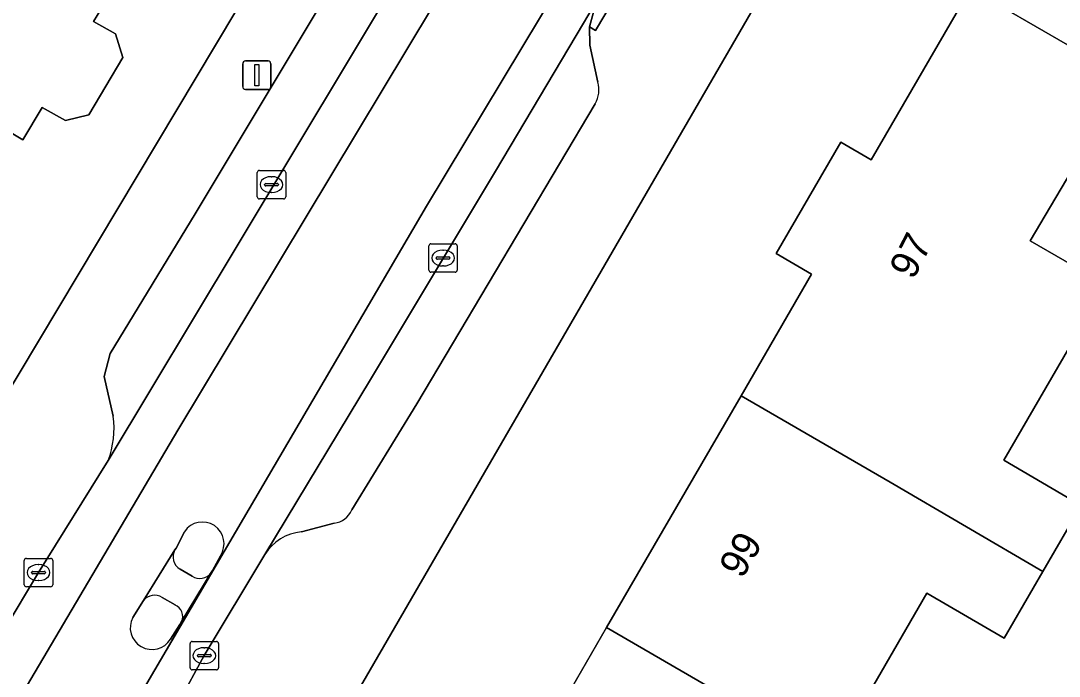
# Model space of a CAD drawing. Extents: x 160349 to 161355, y 381727 to 382854.
# Drawn here: x 160778.71 to 160815.25, y 382183.88 to 382206.95 of the extents above; entities that cross this region are included whole.
import ezdxf

# ---------------------------------------------------------------- set-up
doc = ezdxf.new("R2010")
doc.units = 0
for name, color, linetype in [('IMGEO_Erf', 7, 'Continuous'), ('IMGEO_Kolk', 7, 'Continuous'), ('IMGEO_Lichtmast', 7, 'Continuous'), ('IMGEO_Pand', 7, 'Continuous'), ('IMGEO_Pand_nummerreeks', 7, 'Continuous'), ('IMGEO_Parkeervlak_open', 7, 'Continuous'), ('IMGEO_Rijbaan_lokaal_gesloten', 7, 'Continuous'), ('IMGEO_Verkeerseiland_open', 7, 'Continuous'), ('IMGEO_Voetpad_open', 7, 'Continuous')]:
    doc.layers.add(name, color=color, linetype=linetype)

msp = doc.modelspace()

# ---------------------------------------------------------------- linework, layer by layer
at = {"layer": 'IMGEO_Erf'}
for points in [[(160933.344, 382182.327), (160924.218, 382191.389), (160906.426, 382206.128), (160902.418, 382205.455), (160886.177, 382214.66), (160875.171, 382221.124), (160873.887, 382226.28), (160832.686, 382250), (160830.042, 382251.522), (160829.161, 382250), (160786.376, 382176.128), (160847.679, 382140.543), (160850.05, 382144.635)], [(160761.313, 382208.139), (160764.737, 382206.09), (160765.095, 382206.689), (160769.767, 382203.894), (160771.061, 382206.058), (160774.047, 382204.271), (160778.338, 382201.704), (160775.107, 382196.304), (160771.946, 382191.02), (160769.713, 382187.288), (160767.853, 382186.821), (160772.407, 382184.113), (160794.573, 382221.181)], [(160781.915, 382207.991), (160781.273, 382206.918), (160782.047, 382206.482), (160782.296, 382205.652), (160781.107, 382203.64), (160780.279, 382203.438), (160779.466, 382203.898), (160778.785, 382202.76), (160774.494, 382205.327), (160771.787, 382206.947), (160768.599, 382208.851)], [(160796.673, 382181.019), (160799.321, 382185.589), (160804.051, 382193.749), (160806.533, 382198.033), (160805.285, 382198.756), (160807.566, 382202.676), (160808.629, 382202.058), (160812.129, 382208.085), (160817.811, 382204.787)], [(160817.455, 382204.671), (160814.224, 382199.199), (160816.882, 382197.66), (160813.3, 382191.479), (160816.016, 382189.892), (160814.665, 382187.559), (160813.31, 382185.219), (160810.592, 382186.807), (160807.24, 382181.022)]]:
    msp.add_lwpolyline(points, dxfattribs=at)
at = {"layer": 'IMGEO_Kolk'}
for p, q in [((160787.029, 382200.754), (160787.029, 382201.606)), ((160787.104, 382201.68), (160787.956, 382201.68)), ((160787.517, 382201.46), (160787.542, 382201.46)), ((160788.03, 382201.606), (160788.03, 382200.754)), ((160787.288, 382201.174), (160787.288, 382201.186)), ((160787.726, 382201.137), (160787.328, 382201.137)), ((160787.331, 382201.223), (160787.729, 382201.223)), ((160787.772, 382201.186), (160787.772, 382201.174)), ((160787.54, 382200.9), (160787.515, 382200.9)), ((160787.956, 382200.68), (160787.104, 382200.68)), ((160793.066, 382198.171), (160793.066, 382199.023)), ((160793.141, 382199.097), (160793.993, 382199.097)), ((160794.067, 382199.023), (160794.067, 382198.171)), ((160793.325, 382198.591), (160793.325, 382198.603)), ((160793.763, 382198.554), (160793.365, 382198.554)), ((160793.368, 382198.64), (160793.766, 382198.64)), ((160793.554, 382198.877), (160793.579, 382198.877)), ((160793.809, 382198.603), (160793.809, 382198.591)), ((160793.577, 382198.317), (160793.552, 382198.317)), ((160793.993, 382198.097), (160793.141, 382198.097)), ((160778.832, 382187.101), (160778.832, 382187.953)), ((160778.907, 382188.027), (160779.759, 382188.027)), ((160779.833, 382187.953), (160779.833, 382187.101)), ((160779.32, 382187.807), (160779.345, 382187.807)), ((160779.091, 382187.521), (160779.091, 382187.533)), ((160779.529, 382187.484), (160779.131, 382187.484)), ((160779.134, 382187.57), (160779.532, 382187.57)), ((160779.343, 382187.247), (160779.318, 382187.247)), ((160779.575, 382187.533), (160779.575, 382187.521)), ((160779.759, 382187.027), (160778.907, 382187.027)), ((160784.667, 382184.178), (160784.667, 382185.03)), ((160784.742, 382185.104), (160785.594, 382185.104)), ((160785.668, 382185.03), (160785.668, 382184.178)), ((160785.155, 382184.884), (160785.18, 382184.884)), ((160784.926, 382184.598), (160784.926, 382184.61)), ((160785.364, 382184.561), (160784.966, 382184.561)), ((160784.969, 382184.647), (160785.367, 382184.647)), ((160785.178, 382184.324), (160785.153, 382184.324)), ((160785.41, 382184.61), (160785.41, 382184.598)), ((160785.594, 382184.104), (160784.742, 382184.104))]:
    msp.add_line(p, q, dxfattribs=at)
for points in [[(160787.029, 382200.754), (160787.029, 382201.606)], [(160787.104, 382201.68), (160787.956, 382201.68)], [(160788.03, 382201.606), (160788.03, 382200.754)], [(160787.956, 382200.68), (160787.104, 382200.68)], [(160793.066, 382198.171), (160793.066, 382199.023)], [(160793.141, 382199.097), (160793.993, 382199.097)], [(160794.067, 382199.023), (160794.067, 382198.171)], [(160793.993, 382198.097), (160793.141, 382198.097)], [(160778.832, 382187.101), (160778.832, 382187.953)], [(160778.907, 382188.027), (160779.759, 382188.027)], [(160779.833, 382187.953), (160779.833, 382187.101)], [(160779.759, 382187.027), (160778.907, 382187.027)], [(160784.667, 382184.178), (160784.667, 382185.03)], [(160784.742, 382185.104), (160785.594, 382185.104)], [(160785.668, 382185.03), (160785.668, 382184.178)], [(160785.594, 382184.104), (160784.742, 382184.104)]]:
    msp.add_lwpolyline(points, dxfattribs=at)
for centre, radius, start, end in [((160787.106, 382201.604), 0.0765, 91.552, 178.448), ((160787.106, 382201.604), 0.0765, 91.552, 178.448), ((160787.954, 382201.604), 0.0765, 1.552, 88.448), ((160787.954, 382201.604), 0.0765, 1.552, 88.448), ((160787.328, 382201.183), 0.0403, 85.8775, 175.7526), ((160787.325, 382201.173), 0.0366, 178.938, 274.7102), ((160787.729, 382201.18), 0.043, 264.8664, 352.4533), ((160787.733, 382201.185), 0.0386, 1.7309, 96.639), ((160787.106, 382200.756), 0.0765, 181.552, 268.448), ((160787.106, 382200.756), 0.0765, 181.552, 268.448), ((160787.954, 382200.756), 0.0765, 271.552, 358.448), ((160787.954, 382200.756), 0.0765, 271.552, 358.448), ((160793.143, 382199.021), 0.0765, 91.552, 178.448), ((160793.143, 382199.021), 0.0765, 91.552, 178.448), ((160793.991, 382199.021), 0.0765, 1.552, 88.448), ((160793.991, 382199.021), 0.0765, 1.552, 88.448), ((160793.365, 382198.6), 0.0403, 85.8775, 175.7526), ((160793.362, 382198.59), 0.0366, 178.938, 274.7102), ((160793.766, 382198.597), 0.043, 264.8664, 352.4533), ((160793.77, 382198.602), 0.0386, 1.7309, 96.639), ((160793.143, 382198.173), 0.0765, 181.552, 268.448), ((160793.143, 382198.173), 0.0765, 181.552, 268.448), ((160793.991, 382198.173), 0.0765, 271.552, 358.448), ((160793.991, 382198.173), 0.0765, 271.552, 358.448), ((160778.909, 382187.951), 0.0765, 91.552, 178.448), ((160778.909, 382187.951), 0.0765, 91.552, 178.448), ((160779.757, 382187.951), 0.0765, 1.552, 88.448), ((160779.757, 382187.951), 0.0765, 1.552, 88.448), ((160779.131, 382187.53), 0.0403, 85.8775, 175.7526), ((160779.128, 382187.52), 0.0366, 178.938, 274.7102), ((160779.532, 382187.527), 0.043, 264.8664, 352.4533), ((160779.536, 382187.532), 0.0386, 1.7309, 96.639), ((160778.909, 382187.103), 0.0765, 181.552, 268.448), ((160778.909, 382187.103), 0.0765, 181.552, 268.448), ((160779.757, 382187.103), 0.0765, 271.552, 358.448), ((160779.757, 382187.103), 0.0765, 271.552, 358.448), ((160784.744, 382185.028), 0.0765, 91.552, 178.448), ((160784.744, 382185.028), 0.0765, 91.552, 178.448), ((160785.592, 382185.028), 0.0765, 1.552, 88.448), ((160785.592, 382185.028), 0.0765, 1.552, 88.448), ((160784.966, 382184.607), 0.0403, 85.8775, 175.7526), ((160784.963, 382184.597), 0.0366, 178.938, 274.7102), ((160785.367, 382184.604), 0.043, 264.8664, 352.4533), ((160785.371, 382184.609), 0.0386, 1.7309, 96.639), ((160784.744, 382184.18), 0.0765, 181.552, 268.448), ((160784.744, 382184.18), 0.0765, 181.552, 268.448), ((160785.592, 382184.18), 0.0765, 271.552, 358.448), ((160785.592, 382184.18), 0.0765, 271.552, 358.448)]:
    msp.add_arc(centre, radius, start, end, dxfattribs=at)
for centre, major_axis, ratio, start_param, end_param in [((160787.516, 382201.18), (-0.387, 0.002), 0.722429, 4.712389, 7.853982), ((160787.541, 382201.18), (-0.39, 0.002), 0.717154, 1.570796, 4.712389), ((160793.553, 382198.597), (-0.387, 0.002), 0.722429, 4.712389, 7.853982), ((160793.578, 382198.597), (-0.39, 0.002), 0.717154, 1.570796, 4.712389), ((160779.319, 382187.527), (-0.387, 0.002), 0.722429, 4.712389, 7.853982), ((160779.344, 382187.527), (-0.39, 0.002), 0.717154, 1.570796, 4.712389), ((160785.154, 382184.604), (-0.387, 0.002), 0.722429, 4.712389, 7.853982), ((160785.179, 382184.604), (-0.39, 0.002), 0.717154, 1.570796, 4.712389)]:
    msp.add_ellipse(centre, major_axis=major_axis, ratio=ratio, start_param=start_param, end_param=end_param, dxfattribs=at)
at = {"layer": 'IMGEO_Lichtmast'}
for p, q in [((160786.618, 382205.531), (160787.408, 382205.531)), ((160787.408, 382205.531), (160786.618, 382205.531)), ((160786.518, 382204.631), (160786.518, 382205.431)), ((160786.518, 382205.431), (160786.518, 382204.631)), ((160787.508, 382205.431), (160787.508, 382204.631)), ((160787.508, 382204.631), (160787.508, 382205.431)), ((160787.408, 382204.531), (160786.618, 382204.531)), ((160786.618, 382204.531), (160787.408, 382204.531))]:
    msp.add_line(p, q, dxfattribs=at)
msp.add_lwpolyline([(160786.938, 382205.406), (160787.088, 382205.406), (160787.088, 382204.656), (160786.938, 382204.656), (160786.938, 382205.406)], dxfattribs=at)
for centre, start, end in [((160786.618, 382205.431), 90, 180), ((160786.618, 382205.431), 90, 180), ((160787.408, 382205.431), 0, 90), ((160787.408, 382205.431), 360, 90), ((160786.618, 382204.631), 180, 270), ((160786.618, 382204.631), 180, 270), ((160787.408, 382204.631), 270, 0), ((160787.408, 382204.631), 270, 0)]:
    msp.add_arc(centre, 0.1, start, end, dxfattribs=at)
at = {"layer": 'IMGEO_Pand'}
for points in [[(160771.727, 382214.075), (160771.622, 382213.901), (160771.376, 382213.49), (160770.149, 382211.44), (160768.554, 382212.392), (160767.004, 382209.803), (160768.599, 382208.851), (160771.787, 382206.947), (160774.494, 382205.327), (160778.785, 382202.76), (160779.466, 382203.898), (160780.279, 382203.438), (160781.107, 382203.64), (160782.296, 382205.652), (160782.047, 382206.482), (160781.273, 382206.918), (160781.915, 382207.991)], [(160804.051, 382193.749), (160809.301, 382190.706), (160814.665, 382187.559), (160816.016, 382189.892), (160813.3, 382191.479), (160816.882, 382197.66), (160814.224, 382199.199), (160817.455, 382204.671), (160817.671, 382204.545), (160817.811, 382204.787), (160812.129, 382208.085), (160808.629, 382202.058), (160807.566, 382202.676), (160805.285, 382198.756), (160806.533, 382198.033)], [(160807.24, 382181.022), (160810.592, 382186.807), (160813.31, 382185.219), (160814.665, 382187.559), (160809.301, 382190.706), (160804.051, 382193.749), (160799.321, 382185.589), (160804.574, 382182.544)], [(160807.24, 382181.022), (160804.574, 382182.544), (160799.321, 382185.589), (160796.673, 382181.019), (160795.36, 382181.78), (160793.201, 382178.055), (160799.769, 382174.25), (160802.425, 382172.712), (160804.134, 382175.663), (160804.325, 382175.553), (160804.486, 382175.83), (160804.296, 382175.941), (160804.773, 382176.764), (160804.263, 382177.06), (160805.05, 382178.419), (160805.561, 382178.124), (160805.782, 382178.505), (160808.214, 382177.097), (160809.683, 382179.634)]]:
    msp.add_lwpolyline(points, close=True, dxfattribs=at)
at = {"layer": 'IMGEO_Parkeervlak_open'}
for points in [[(160781.786, 382191.466), (160786.323, 382199.028), (160798.28, 382218.963), (160805.521, 382230.961), (160817.325, 382250.962), (160826.186, 382266.882), (160838.167, 382290.047), (160842.376, 382298.812)], [(160839.013, 382296.685), (160829.617, 382277.989), (160823.877, 382267.074), (160820.834, 382261.421), (160816.429, 382253.709), (160815.075, 382251.417), (160814.238, 382250), (160812.776, 382247.525), (160807.918, 382239.299), (160796.693, 382219.912), (160784.85, 382200.156), (160781.859, 382195.236), (160781.646, 382194.422), (160781.963, 382193.031)], [(160799.013, 382204.786), (160798.729, 382206.085), (160798.713, 382206.735), (160798.962, 382207.633), (160798.503, 382206.859), (160795.414, 382201.651), (160791.017, 382194.317), (160787.293, 382188.166)], [(160790.359, 382189.731), (160792.641, 382193.471), (160798.922, 382204.027)], [(160788.58, 382188.958), (160789.734, 382189.265)]]:
    msp.add_lwpolyline(points, dxfattribs=at)
for centre, radius, start, end in [((160798.037, 382204.518), 1.012, 330.9649, 15.3615), ((160778.647, 382192.614), 3.343, 339.9207, 7.1739), ((160789.65, 382190.03), 0.769, 276.2553, 337.1612), ((160788.746, 382187.246), 1.72, 95.5483, 147.6668)]:
    msp.add_arc(centre, radius, start, end, dxfattribs=at)
at = {"layer": 'IMGEO_Rijbaan_lokaal_gesloten'}
for points in [[(160812.989, 382240.37), (160784.239, 382192.537), (160777.906, 382181.828), (160776.425, 382182.776), (160776.168, 382182.334), (160769.164, 382170.249), (160770.494, 382169.628), (160766.428, 382162.546), (160760.731, 382152.677), (160755.42, 382142.776), (160751.633, 382135.727), (160748.813, 382130.153), (160747.076, 382126.71), (160742.756, 382117.768), (160731.871, 382093.997), (160727.444, 382083.882), (160724.887, 382077.653), (160720.494, 382066.374), (160710.123, 382039.204), (160704.275, 382025.25)], [(160798.28, 382218.963), (160786.323, 382199.028), (160781.786, 382191.466), (160779.334, 382187.527), (160778.121, 382185.508), (160776.823, 382183.463), (160776.425, 382182.776), (160777.906, 382181.828), (160784.239, 382192.537), (160812.989, 382240.37)], [(160805.748, 382221.628), (160792.985, 382200.423), (160781.379, 382180.62), (160782.592, 382179.909), (160782.82, 382180.287), (160785.167, 382184.605), (160787.293, 382188.166), (160791.017, 382194.317), (160795.414, 382201.651), (160798.503, 382206.859), (160798.962, 382207.633)], [(160792.985, 382200.423), (160805.748, 382221.628)], [(160696.524, 381990.659), (160696.749, 381990.258), (160698.267, 381993.805), (160702.724, 382005.472), (160701.297, 382006.186), (160706.444, 382018.907), (160712.871, 382036.35), (160718.969, 382052.415), (160728.018, 382076.284), (160733.461, 382089.005), (160737.526, 382098.251), (160743.231, 382110.677), (160748.477, 382121.661), (160754.903, 382134.448), (160758.33, 382141.071), (160759.953, 382144.071), (160767.084, 382156.956), (160773.018, 382167.169), (160774.485, 382166.436), (160782.592, 382179.909), (160781.379, 382180.62), (160792.985, 382200.423)], [(160782.651, 382185.948), (160783.024, 382186.545), (160784.129, 382188.323), (160784.171, 382188.39), (160784.464, 382188.966)], [(160785.732, 382188.122), (160785.452, 382187.605)], [(160785.452, 382187.605), (160785.405, 382187.526), (160784.367, 382185.801), (160784.307, 382185.702), (160783.978, 382185.184)]]:
    msp.add_lwpolyline(points, dxfattribs=at)
for centre, radius, start, end in [((160785.098, 382188.544), 0.762, 326.3517, 146.3517), ((160783.326, 382185.587), 0.766, 151.8557, 328.2832)]:
    msp.add_arc(centre, radius, start, end, dxfattribs=at)
at = {"layer": 'IMGEO_Verkeerseiland_open'}
for points in [[(160784.464, 382188.966), (160784.171, 382188.39), (160784.129, 382188.323)], [(160784.129, 382188.323), (160783.024, 382186.545)], [(160785.405, 382187.526), (160785.452, 382187.605), (160785.732, 382188.122)], [(160784.737, 382187.404), (160784.311, 382187.652)], [(160784.311, 382187.652), (160784.737, 382187.404)], [(160784.367, 382185.801), (160785.405, 382187.526)], [(160783.024, 382186.545), (160782.651, 382185.948)], [(160783.683, 382186.65), (160784.138, 382186.386)], [(160784.138, 382186.386), (160783.683, 382186.65)], [(160783.978, 382185.184), (160784.307, 382185.702), (160784.367, 382185.801)]]:
    msp.add_lwpolyline(points, dxfattribs=at)
for centre, radius, start, end in [((160785.098, 382188.544), 0.762, 326.3517, 146.3517), ((160784.556, 382188.079), 0.492, 150.1813, 240.1699), ((160784.556, 382188.079), 0.492, 150.1813, 240.1699), ((160785.011, 382187.793), 0.476, 234.8447, 325.8555), ((160785.011, 382187.793), 0.476, 234.8447, 325.8555), ((160783.412, 382186.227), 0.502, 57.3746, 140.7313), ((160783.412, 382186.227), 0.502, 57.3746, 140.7313), ((160783.968, 382185.982), 0.438, 335.5793, 67.1767), ((160783.968, 382185.982), 0.438, 335.5793, 67.1767), ((160783.326, 382185.587), 0.766, 151.8557, 328.2832)]:
    msp.add_arc(centre, radius, start, end, dxfattribs=at)
at = {"layer": 'IMGEO_Voetpad_open'}
for points in [[(160843.818, 382306.679), (160846.821, 382312.974), (160844.409, 382314.087), (160840.283, 382305.069), (160838.339, 382300.821), (160828.746, 382282.08), (160815.558, 382257.479), (160811.234, 382250), (160794.573, 382221.181), (160772.407, 382184.113), (160770.967, 382181.708)], [(160781.963, 382193.031), (160781.646, 382194.422), (160781.859, 382195.236), (160784.85, 382200.156), (160796.693, 382219.912), (160807.918, 382239.299), (160812.776, 382247.525), (160812.345, 382247.775), (160813.659, 382250), (160814.643, 382251.667), (160815.075, 382251.417), (160816.429, 382253.709), (160820.834, 382261.421), (160823.877, 382267.074), (160829.617, 382277.989), (160839.013, 382296.685)], [(160785.65, 382171.897), (160786.376, 382176.128), (160829.161, 382250)], [(160824.181, 382246.765), (160816.635, 382233.947), (160808.563, 382220.384), (160808.01, 382219.333), (160806.44, 382220.243), (160804.931, 382217.699), (160805.361, 382217.445), (160802.26, 382212.214), (160801.83, 382212.468), (160800.434, 382210.12), (160800.864, 382209.866), (160798.933, 382206.605), (160798.713, 382206.735), (160798.729, 382206.085), (160799.013, 382204.786)], [(160798.922, 382204.027), (160792.641, 382193.471), (160790.359, 382189.731)], [(160778.121, 382185.508), (160779.334, 382187.527), (160781.786, 382191.466)], [(160789.734, 382189.265), (160788.58, 382188.958)], [(160787.293, 382188.166), (160785.167, 382184.605), (160782.82, 382180.287)]]:
    msp.add_lwpolyline(points, dxfattribs=at)
msp.add_lwpolyline([(160798.713, 382206.735), (160798.933, 382206.605), (160800.864, 382209.866), (160800.434, 382210.12), (160798.962, 382207.633)], close=True, dxfattribs=at)
for centre, radius, start, end in [((160798.037, 382204.518), 1.012, 330.9649, 15.3615), ((160778.647, 382192.614), 3.343, 339.9207, 7.1739), ((160789.65, 382190.03), 0.769, 276.2553, 337.1612), ((160788.746, 382187.246), 1.72, 95.5483, 147.6668)]:
    msp.add_arc(centre, radius, start, end, dxfattribs=at)

# ---------------------------------------------------------------- texts
at = {"layer": 'IMGEO_Pand_nummerreeks'}
for s, rotation, p in [('97', 62.4939, (160810.109, 382197.797)), ('99', 59.9063, (160804.091, 382187.276))]:
    msp.add_text(s, height=1, rotation=rotation, dxfattribs=at).set_placement(p)

doc.saveas('drawing.dxf')
